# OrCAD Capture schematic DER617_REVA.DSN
size D
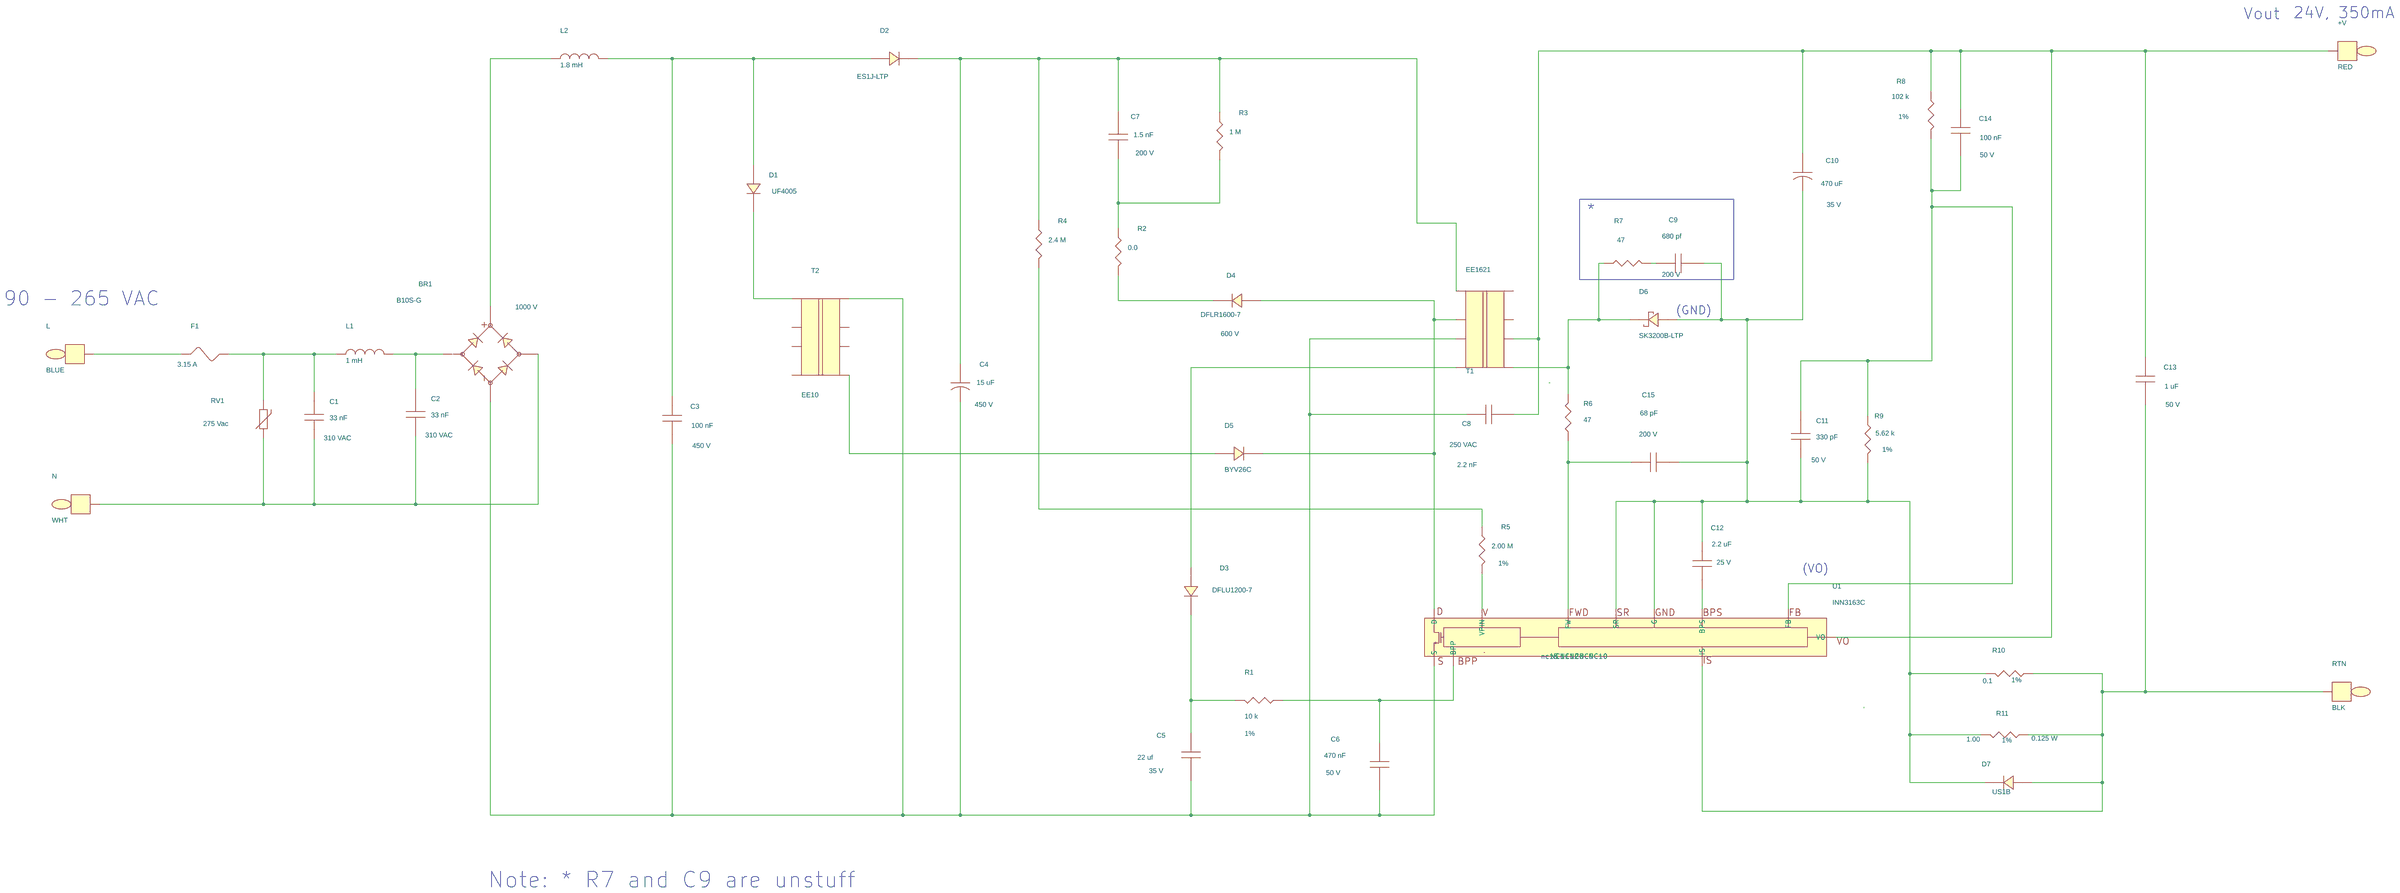
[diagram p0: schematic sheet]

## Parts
+V  RED  [pitpkeystone100x100]
BR1  B10S-G  [pismsoic4]
C1  33 nF  [pi_np_cap400x160ls300d040]
C2  33 nF  [pi_np_cap400x160ls300d040]
C3  100 nF  [pinpcaprad440x200300040]
C4  15 uF  [pipolcapcyld400ls200040]
C5  22 uf  [pismc1206]
C6  470 nF  [pismc0805]
C7  1.5 nF  [pismc0805]
C8  2.2 nF  [pinpycaprad540x290ls400040]
C9  680 pf  [pismc0805]
C10  470 uF  [pipolcapcyld400ls200040]
C11  330 pF  [pismc0603]
C12  2.2 uF  [pismc1206]
C13  1 uF  [pismc0805]
C14  100 nF  [pismc0603]
C15  68 pF  [pismc0603]
D1  UF4005  [pidv200x110x040do41]
D2  ES1J-LTP  [pismdo214ac12]
D3  DFLU1200-7  [pismddflr120012]
D4  DFLR1600-7  [pismddflr120012]
D5  BYV26C  [pidv200x150x040sod57]
D6  SK3200B-LTP  [pismsmb]
D7  US1B  [pismdsma]
F1  3.15 A  [pi_v_ax_3-6x10_145ls200d030]
L  BLUE  [pitpkeystone100x100]
L1  1 mH  [pichoke030dials200035]
L2  1.8 mH  [pi_choke_2p_ls200d300]
N  WHT  [pitpkeystone100x100]
R1  10 k  [pismr0805]
R2  0.0  [pismr0805]
R3  1 M  [pismr1206]
R4  2.4 M  [pi14wvresd100ls100d030]
R5  2.00 M  [pismr1206]
R6  47  [pismr0805]
R7  47  [pismr1206]
R8  102 k  [pismr0603]
R9  5.62 k  [pismr0603]
R10  0.1  [pismr0805]
R11  1.00  [pismr0805]
RTN  BLK  [pitpkeystone100x100]
RV1  275 Vac  [pidisc350x160ls210x140040]
T1  EE1621  [pi_bobbin_ee1621_8p]
T2  EE10  [pi_bobbin_ee10_8p]
U1  INN3163C  [pi_ic_insop_24d]

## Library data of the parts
+V = TESTPOINT: Part Number: 35-00080-00
BR1 = DIODE_BRIDGE_~~+-: ALT_SYMBOLS: pi_sm_soic4_slot; Disp_Voltage: 1000 V; FPLIST: pismsoic4,pi_sm_soic4_slot; Part Number: 15-00818-00
C1 C2 = CAP_NP: Disp_Voltage: 310 VAC; Part Number: 20-01114-00; Voltage: 310 VAC
C3 = CAP_NP: ALT_SYMBOLS: pinpcaprad440x200300040h; Disp_Voltage: 450 V; FPLIST: pinpcaprad440x200300040,pinpcaprad440x200300040h; Part Number: 20-08690-00; Voltage: 450 V
C4 = CAP_POL: ALT_SYMBOLS: pipolcapcyld400ls200040800h; Disp_Voltage: 450 V; FPLIST: pipolcapcyld400ls200040,pipolcapcyld400ls200040800h; Part Number: 20-09034-00; Voltage: 450 V
C5 = CAP_NP: Disp_Voltage: 35 V; Part Number: 20-01138-00; Voltage: 35 V
C6 = CAP_NP: Disp_Voltage: 50 V; Part Number: 20-00896-00; Voltage: 50 V
C7 = CAP_NP: Disp_Voltage: 200 V; Part Number: 20-01150-00; Voltage: 200 V
C8 = CAP_NP: ALT_SYMBOLS: pinpycaprad540x290ls400040h; COMPGROUP: 3; Disp_Voltage: 250 VAC; FPLIST: pinpycaprad540x290ls400040,pinpycaprad540x290ls400040h; Part Number: 20-00376-00; Voltage: 250 VAC
C9 = CAP_NP: Disp_Voltage: 200 V; PCB Editor PCBFP: pismc0603; Part Number: 24-00025-00; Voltage: 200 V
C10 = CAP_POL: ALT_SYMBOLS: pipolcapcyld400ls200040800h; COMPGROUP: 3; Disp_Voltage: 35 V; FPLIST: pipolcapcyld400ls200040,pipolcapcyld400ls200040800h; Part Number: 20-00123-00; Voltage: 35 V
C11 = CAP_NP: Disp_Voltage: 50 V; Part Number: 20-08676-00; Voltage: 50 V
C12 = CAP_NP: Disp_Voltage: 25 V; Part Number: 20-01034-00; Voltage: 25 V
C13 = CAP_NP: Disp_Voltage: 50 V; Part Number: 20-01022-00; Voltage: 50 V
C14 = CAP_NP: Disp_Voltage: 50 V; Part Number: 20-00936-00; Voltage: 50 V
C15 = CAP_NP: Disp_Voltage: 200 V; Part Number: 20-09033-00; Voltage: 200 V
D1 = DIODE: ALT_SYMBOLS: pidax475x125040do41,pidax390x125040do41; COMPGROUP: 1; FPLIST: pidv200x110x040do41,pidax475x125040do41,pidax390x125040do41; Part Number: 15-00109-00
D2 = DIODE: Part Number: 15-01071-00
D3 = DIODE: COMPGROUP: 1; Part Number: 15-01043-00
D4 = DIODE: Disp_Voltage: 600 V; Part Number: 15-00826-00
D5 = DIODE: ALT_SYMBOLS: pidax425x150040sod57; COMPGROUP: 1; FPLIST: pidv200x150x040sod57,pidax425x150040sod57; Part Number: 15-00128-00
D6 = DIODE_SCHOTTKY: Part Number: 15-00877-00
D7 = DIODE: Part Number: 15-00491-00
F1 = FUSE: ALT_SYMBOLS: pi_axial_3_6x10_145ls500d030; FPLIST: pi_v_ax_3-6x10_145ls200d030,pi_axial_3_6x10_145ls500d030; Part Number: 40-00064-00; Voltage: 250 V
L = TESTPOINT: Part Number: 35-00397-00
L1 = INDUCTOR: Part Number: 30-00169-00
L2 = INDUCTOR: Part Number: 30-00406-00
N = TESTPOINT: Part Number: 35-00081-00
R1 = R: Disp_Tol: 1%; Part Number: 05-00684-00
R2 = R: Part Number: 05-03159-00
R3 = R: Part Number: 05-01424-00
R4 = R: ALT_SYMBOLS: pi14wvresd100ls200d030,pi14wresd100ls400d030,pi14wresd100ls500d030; FPLIST: pi14wvresd100ls100d030,pi14wvresd100ls200d030,pi14wresd100ls400d030,pi14wresd100ls500d030; Part Number: 05-03112-00
R5 = R: Disp_Tol: 1%; Part Number: 05-03156-00
R6 = R: Part Number: 05-01487-00
R7 = R: Part Number: 05-01320-00
R8 = R: Disp_Tol: 1%; Part Number: 05-01175-00
R9 = R: Disp_Tol: 1%; Part Number: 05-01150-00
R10 = R: Disp_Tol: 1%; Part Number: 05-06457-00
R11 = R: Disp_Power: 0.125 W; Disp_Tol: 1%; Part Number: 05-06377-00
RTN = TESTPOINT: Part Number: 35-00079-00
RV1 = VARISTOR: ALT_SYMBOLS: pi_disc_354x220_ls220x10_040_h; FPLIST: pidisc350x160ls210x140040,pi_disc_354x220_ls220x10_040_h; Part Number: 85-00015-00
T1 = BEE16_8P_GENERIC: Part Number: 25-01044-00
T2 = BEE10_8P_VERT: Part Number: 25-01068-00
U1 = DEV_Inno3CE: Part Number: 10-01030-00

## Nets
NC8: U1.8(NC8)
NC9: U1.9(NC9)
NC10: U1.10(NC10)
NC11: U1.11(NC11)
NC12: U1.12(NC12)
NC15: U1.15(nc15)
N10967118: C5.1 D3.1 R1.1
N10967192: D4.1 R2.2
N10967272: D4.2 D5.1 T1.2 U1.24(D)
N10967292: C4.1 C7.2 D2.1 R3.1 R4.1 T1.1
N10967352: C6.1 R1.2 U1.14(BPP)
N10967360: C11.2 C14.2 R8.2 R9.1 U1.3(FB)
N10967588: +V.1 C8.2 C10.1 C13.1 C14.1 R8.1 T1.6 U1.6(VO)
N10967778: C9.2 C10.2 C11.1 C12.1 C15.2 D6.2 D7.1 R9.2 R10.2 R11.2 U1.2(G) U1.5(SR)
N10967790: C13.2 D7.2 R10.1 R11.1 RTN.1 U1.1(IS)
N10968562: BR1.4 C3.2 C4.2 C5.2 C6.2 C8.1 T1.3 T2.8 U1.16(S)
N10970421: F1.1 L.1
N10970473: BR1.1 C1.1 C2.1 N.1 RV1.1
N10970939: C3.1 D1.2 D2.2 L2.2
N10975943: C7.1 R2.1 R3.2
N11207743: C1.2 F1.2 L1.1 RV1.2
N11207906: BR1.3 L2.1
N11317958: R5.2 U1.13(VPIN)
N11319179: C12.2 U1.4(BPS)
N11357409: D6.1 R6.2 R7.2 T1.5
N11358599: C15.1 R6.1 U1.7(FW)
N11365787: R4.2 R5.1
N11380849: D3.2 T1.4
N11384119: BR1.2 C2.2 L1.2
N11395895: D1.1 T2.1
N11395976: D5.2 T2.5
N11401626: C9.1 R7.1

Not connected (* = marked no-connect by the designer): T1 7 8; T2 2 3 4 6 7

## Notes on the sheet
- Vout
- 24V, 350mA
- *
- 90 - 265 VAC
- (GND)
- (VO)
- Note: * R7 and C9 are unstuff
